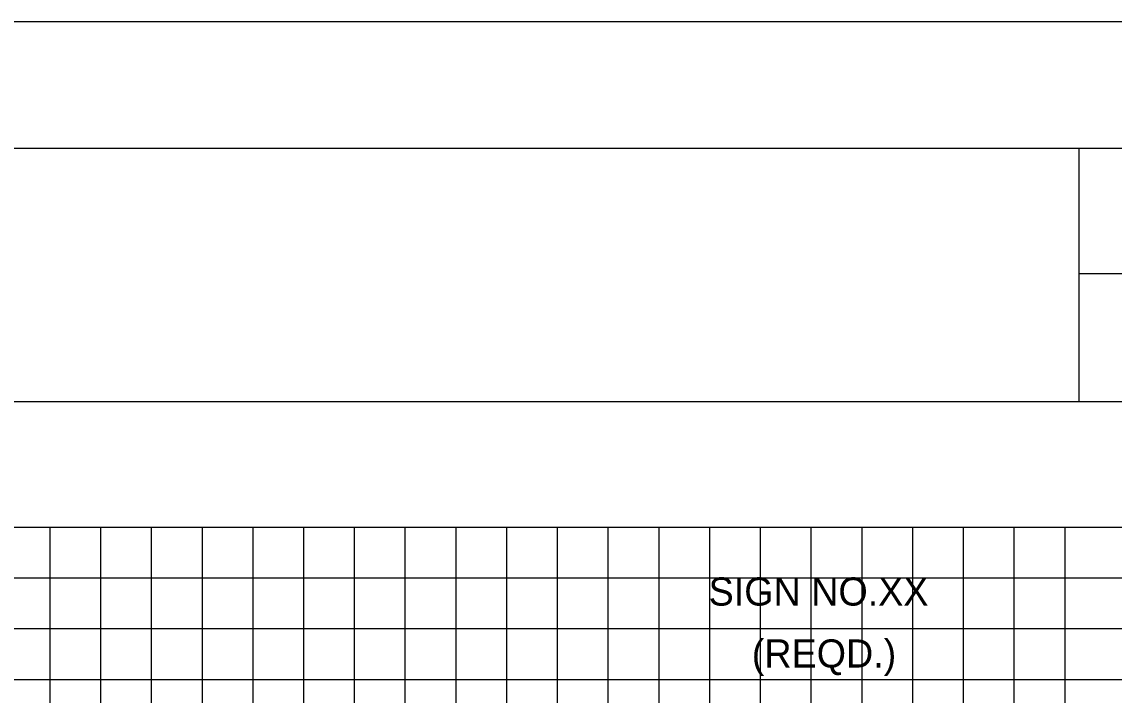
# Model space of a CAD drawing. Extents: x 2193008 to 2198143, y 1236112 to 1237864.
# Drawn here: x 2195111.75 to 2195154.8, y 1237311.48 to 1237338.04 of the extents above; entities that cross this region are included whole.
import ezdxf

# ---------------------------------------------------------------- set-up
doc = ezdxf.new("R2010")
doc.units = 0
for name, color, linetype in [('Level 55', 7, 'Continuous'), ('Level 6', 7, 'Continuous'), ('M-ROADS', 7, 'Continuous'), ('SHT-BNDRY', 7, 'Continuous')]:
    doc.layers.add(name, color=color, linetype=linetype)

msp = doc.modelspace()

# ---------------------------------------------------------------- linework, layer by layer
msp.add_lwpolyline([(2194882.86, 1237133.046), (2195182.86, 1237133.046), (2195182.86, 1237323.046), (2194882.86, 1237323.046)], close=True)
at = {"layer": 'Level 6'}
for p, q in [((2195153.407, 1237333.036), (2195153.407, 1237323.046)), ((2195192.863, 1237328.097), (2195153.407, 1237328.097)), ((2195192.863, 1237323.046), (2195154.617, 1237323.046))]:
    msp.add_line(p, q, dxfattribs=at)
at = {"layer": 'M-ROADS'}
for p, q in [((2195042.86, 1237318.106), (2195172.86, 1237318.106)), ((2195112.86, 1237258.106), (2195112.86, 1237318.106)), ((2195114.86, 1237258.106), (2195114.86, 1237318.106)), ((2195116.86, 1237258.106), (2195116.86, 1237318.106)), ((2195118.86, 1237258.106), (2195118.86, 1237318.106)), ((2195120.86, 1237258.106), (2195120.86, 1237318.106)), ((2195122.86, 1237258.106), (2195122.86, 1237318.106)), ((2195124.86, 1237258.106), (2195124.86, 1237318.106)), ((2195126.86, 1237258.106), (2195126.86, 1237318.106)), ((2195128.86, 1237258.106), (2195128.86, 1237318.106)), ((2195130.86, 1237258.106), (2195130.86, 1237318.106)), ((2195132.86, 1237258.106), (2195132.86, 1237318.106)), ((2195134.86, 1237258.106), (2195134.86, 1237318.106)), ((2195136.86, 1237258.106), (2195136.86, 1237318.106)), ((2195138.86, 1237258.106), (2195138.86, 1237318.106)), ((2195140.86, 1237258.106), (2195140.86, 1237318.106)), ((2195142.86, 1237258.106), (2195142.86, 1237318.106)), ((2195144.86, 1237258.106), (2195144.86, 1237318.106)), ((2195146.86, 1237258.106), (2195146.86, 1237318.106)), ((2195148.86, 1237258.106), (2195148.86, 1237318.106)), ((2195150.86, 1237258.106), (2195150.86, 1237318.106)), ((2195152.86, 1237258.106), (2195152.86, 1237318.106)), ((2195042.86, 1237316.106), (2195172.86, 1237316.106)), ((2195042.86, 1237314.106), (2195172.86, 1237314.106)), ((2195042.86, 1237312.106), (2195172.86, 1237312.106))]:
    msp.add_line(p, q, dxfattribs=at)
msp.add_lwpolyline([(2194857.863, 1237118.036), (2195197.863, 1237118.036), (2195197.863, 1237338.036), (2194857.863, 1237338.036)], close=True, dxfattribs=at)
at = {"layer": 'SHT-BNDRY'}
msp.add_lwpolyline([(2194870.363, 1237123.036), (2195192.863, 1237123.036), (2195192.863, 1237333.036), (2194870.363, 1237333.036)], close=True, dxfattribs=at)

# ---------------------------------------------------------------- texts
at = {"layer": 'Level 55'}
for s, p in [('SIGN NO.XX', (2195138.814, 1237315.016)), ('(REQD.)', (2195140.516, 1237312.573))]:
    msp.add_text(s, height=1.1105, dxfattribs=at).set_placement(p)

doc.saveas('drawing.dxf')
